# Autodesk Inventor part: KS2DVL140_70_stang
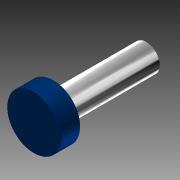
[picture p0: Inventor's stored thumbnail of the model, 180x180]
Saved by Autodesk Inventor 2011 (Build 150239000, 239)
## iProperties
Created: 2010-11
Document SubType Name: Modeling
Designer: TB
Mass: 161.233 g
Surface Area: 236.814 cm^2
Volume: 161.233 cm^3
Density: 1 g/cm^3
Author: TB
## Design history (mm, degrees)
sketch "Sketch2"
  geometry: L1 (-35, -3)-(-35, 3) reference; L2 (-35, -9)-(-35, 9) reference; L3 (-35, 35)-(-324, 35); L4 (-324, 35)-(-324, 0); L5 (-324, 0)-(-35, 0); L6 (-35, 0)-(-35, 35); L7 (-324, 35)-(-272, 35); L8 (-272, 35)-(-272, 70); L9 (-272, 70)-(-324, 70); L10 (-324, 70)-(-324, 35); 1 further point
  constraints: 16 end point, 4 parallel, 2 horizontal, 2 perpendicular, 1 midpoint
  dimensions: "Dia" = 70 diameter of L3 L5; "d3" = 289 distance of L3.start L3.end (computed from Slaglengde, Forlengelse_rør); "StempelDia" = 140 diameter of L9 L5; "StempelLengde" = 52 distance of L8.end L9.end
revolve "Revolution1" sketch "Sketch2" stored, may be unused: angle "d6" = 90 deg
fillet "Fillet1" dims "d7" = 2
sketch "Sketch3"
  geometry: L1 (-324, -68)-(-324, 68) reference; L2 (-324, 0)-(-324.01, 0); L3 (-324, 0)-(-324, 0.01); A1 r 0.01 centre (-324, 0) between (-324, 0.01) and (-324.01, 0); 1 further point
  constraints: 4 end point, 2 point on circle, 1 centre point, 1 midpoint, 1 perpendicular, 1 point on line
  dimensions: "d8" = 0.01 distance of L2.start L2.end; "d9" = 0.01 distance of L2.start L3.end (= d8); "d10" = 0.01 radius of A1 (= d8)
revolve "Revolution2" sketch "Sketch3" stored, may be unused: angle "d11" = 90 deg
body "Solid1"
node "Projected Loop2"
other parameters: "Forlengelse_rør" = 0
